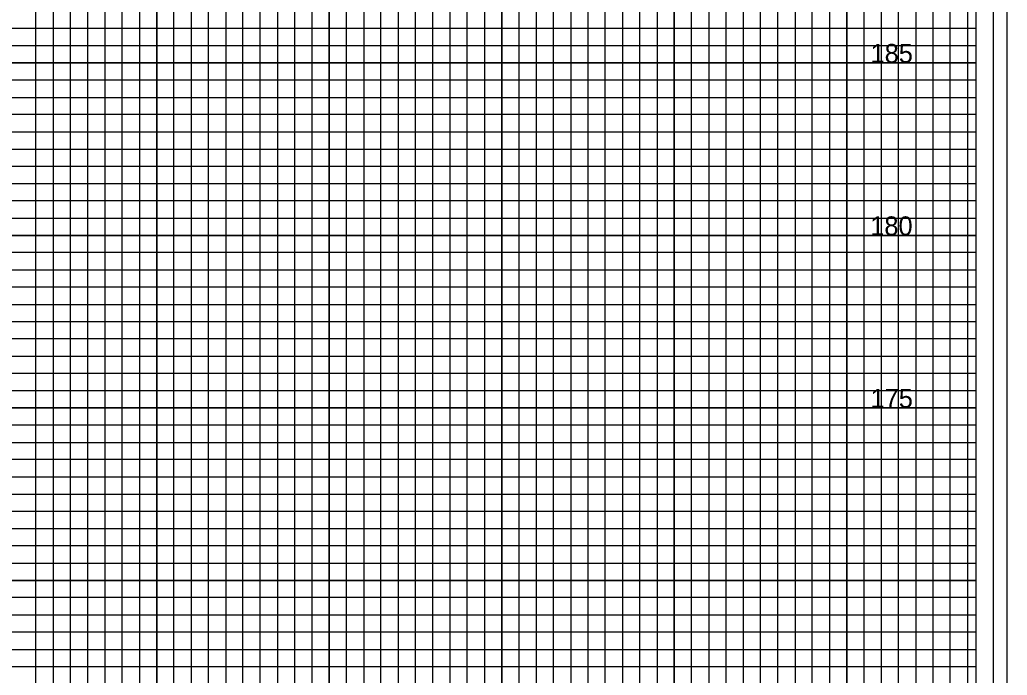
# Model space of a CAD drawing. Extents: x -4 to 103, y -2 to 209.
# Drawn here: x 74.78 to 103.4, y 103.08 to 122.08 of the extents above; entities that cross this region are included whole.
import ezdxf

# ---------------------------------------------------------------- set-up
doc = ezdxf.new("R2010")
doc.units = 0
for name, color, linetype in [('Old_Level_10', 7, 'Continuous'), ('Old_Level_4', 7, 'Continuous'), ('Old_Level_5', 7, 'Continuous'), ('Old_Level_6', 7, 'Continuous'), ('Old_Level_8', 7, 'Continuous'), ('Prop Dimension', 7, 'Continuous'), ('Prop XS Subgrade Earthwork', 7, 'Continuous')]:
    doc.layers.add(name, color=color, linetype=linetype)

msp = doc.modelspace()

# ---------------------------------------------------------------- linework, layer by layer
at = {"layer": 'Old_Level_10'}
for p, q in [((91.25, 70.825), (91.25, 134.25)), ((93.75, 70.825), (93.75, 134.25)), ((96.25, 70.825), (96.25, 134.25)), ((98.75, 70.825), (98.75, 134.25)), ((101.25, 70.825), (101.25, 134.25)), ((76.25, 70.825), (76.25, 132.825)), ((78.75, 70.825), (78.75, 132.825)), ((81.25, 70.825), (81.25, 132.825)), ((83.75, 70.825), (83.75, 132.825)), ((86.25, 70.825), (86.25, 132.825)), ((88.75, 70.825), (88.75, 132.825)), ((0, 120.825), (102.5, 120.825)), ((0, 118.325), (102.5, 118.325)), ((0, 115.825), (102.5, 115.825)), ((0, 113.325), (102.5, 113.325)), ((0, 110.825), (102.5, 110.825)), ((0, 108.325), (102.5, 108.325)), ((0, 105.825), (102.5, 105.825)), ((0, 103.325), (102.5, 103.325))]:
    msp.add_line(p, q, dxfattribs=at)
at = {"layer": 'Old_Level_4'}
msp.add_lwpolyline([(103, 136.825), (-2.8, 136.825), (-2.8, 69.825), (103, 69.825)], close=True, dxfattribs=at)
at = {"layer": 'Old_Level_5'}
msp.add_lwpolyline([(103.4, 138.225), (-3.5, 138.225), (-3.5, 68.4), (103.4, 68.4)], close=True, dxfattribs=at)
at = {"layer": 'Old_Level_6'}
msp.add_lwpolyline([(102.5, 135.825), (0, 135.825), (0, 70.825), (102.5, 70.825)], close=True, dxfattribs=at)
at = {"layer": 'Old_Level_8'}
for points in [[(91.25, 70.825), (91.25, 134.25), (93.75, 134.25), (93.75, 70.825)], [(96.25, 70.825), (96.25, 134.25), (98.75, 134.25), (98.75, 70.825)], [(101.25, 70.825), (101.25, 134.25)], [(76.25, 70.825), (76.25, 132.825), (78.75, 132.825), (78.75, 70.825)], [(81.25, 70.825), (81.25, 132.825), (83.75, 132.825), (83.75, 70.825)], [(86.25, 70.825), (86.25, 132.825), (88.75, 132.825), (88.75, 70.825)], [(0, 118.325), (102.5, 118.325), (102.5, 120.825), (0, 120.825)], [(0, 113.325), (102.5, 113.325), (102.5, 115.825), (0, 115.825)], [(0, 108.325), (102.5, 108.325), (102.5, 110.825), (0, 110.825)], [(0, 103.325), (102.5, 103.325), (102.5, 105.825), (0, 105.825)]]:
    msp.add_lwpolyline(points, dxfattribs=at)
at = {"layer": 'Prop Dimension'}
for points in [[(90.25, 70.825), (90.25, 134.25), (90.75, 134.25), (90.75, 70.825)], [(91.75, 70.825), (91.75, 134.25), (92.25, 134.25), (92.25, 70.825)], [(92.75, 70.825), (92.75, 134.25), (93.25, 134.25), (93.25, 70.825)], [(94.25, 70.825), (94.25, 134.25), (94.75, 134.25), (94.75, 70.825)], [(95.25, 70.825), (95.25, 134.25), (95.75, 134.25), (95.75, 70.825)], [(96.75, 70.825), (96.75, 134.25), (97.25, 134.25), (97.25, 70.825)], [(97.75, 70.825), (97.75, 134.25), (98.25, 134.25), (98.25, 70.825)], [(99.25, 70.825), (99.25, 134.25), (99.75, 134.25), (99.75, 70.825)], [(100.25, 70.825), (100.25, 134.25)], [(100.25, 134.25), (100.75, 134.25), (100.75, 70.825), (101.75, 70.825), (101.75, 134.25), (102.25, 134.25), (102.25, 70.825)], [(75.25, 70.825), (75.25, 132.825), (75.75, 132.825), (75.75, 70.825)], [(76.75, 70.825), (76.75, 132.825), (77.25, 132.825), (77.25, 70.825)], [(77.75, 70.825), (77.75, 132.825), (78.25, 132.825), (78.25, 70.825)], [(79.25, 70.825), (79.25, 132.825), (79.75, 132.825), (79.75, 70.825)], [(80.25, 70.825), (80.25, 132.825), (80.75, 132.825), (80.75, 70.825)], [(81.75, 70.825), (81.75, 132.825), (82.25, 132.825), (82.25, 70.825)], [(82.75, 70.825), (82.75, 132.825), (83.25, 132.825), (83.25, 70.825)], [(84.25, 70.825), (84.25, 132.825), (84.75, 132.825), (84.75, 70.825)], [(85.25, 70.825), (85.25, 132.825), (85.75, 132.825), (85.75, 70.825)], [(86.75, 70.825), (86.75, 132.825), (87.25, 132.825), (87.25, 70.825)], [(87.75, 70.825), (87.75, 132.825), (88.25, 132.825), (88.25, 70.825)], [(89.25, 70.825), (89.25, 132.825), (89.75, 132.825), (89.75, 70.825)], [(0, 121.325), (102.5, 121.325), (102.5, 121.825), (0, 121.825)], [(0, 119.825), (102.5, 119.825), (102.5, 120.325), (0, 120.325)], [(0, 118.825), (102.5, 118.825), (102.5, 119.325), (0, 119.325)], [(0, 117.325), (102.5, 117.325), (102.5, 117.825), (0, 117.825)], [(0, 116.325), (102.5, 116.325), (102.5, 116.825), (0, 116.825)], [(0, 114.825), (102.5, 114.825), (102.5, 115.325), (0, 115.325)], [(0, 113.825), (102.5, 113.825), (102.5, 114.325), (0, 114.325)], [(0, 112.325), (102.5, 112.325), (102.5, 112.825), (0, 112.825)], [(0, 111.325), (102.5, 111.325), (102.5, 111.825), (0, 111.825)], [(0, 109.825), (102.5, 109.825), (102.5, 110.325), (0, 110.325)], [(0, 108.825), (102.5, 108.825), (102.5, 109.325), (0, 109.325)], [(0, 107.325), (102.5, 107.325), (102.5, 107.825), (0, 107.825)], [(0, 106.325), (102.5, 106.325), (102.5, 106.825), (0, 106.825)], [(0, 104.825), (102.5, 104.825), (102.5, 105.325), (0, 105.325)], [(0, 103.825), (102.5, 103.825), (102.5, 104.325), (0, 104.325)]]:
    msp.add_lwpolyline(points, dxfattribs=at)

# ---------------------------------------------------------------- texts
at = {"layer": 'Prop XS Subgrade Earthwork'}
for s, p in [('185', (99.4383, 120.825)), ('180', (99.4296, 115.825)), ('175', (99.4383, 110.825))]:
    msp.add_text(s, height=0.55, dxfattribs=at).set_placement(p)

doc.saveas('drawing.dxf')
